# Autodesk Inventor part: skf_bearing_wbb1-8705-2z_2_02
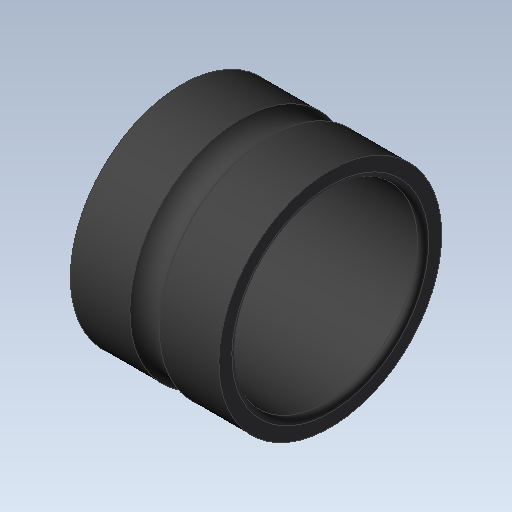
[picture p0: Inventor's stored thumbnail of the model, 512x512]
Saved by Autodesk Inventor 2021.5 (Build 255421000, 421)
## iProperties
Created: 2023-11
Part Number: skf_bearing_wbb1-8705-2z_2_02
Checked By: TraceParts S.A.
Material: Generic
Catalog Web Link: www.traceparts.com
Document SubType Name: Modeling
Designer: TraceParts
Density: 1 g/cm^3
Appearance: Default
Company: TraceParts S.A.
Author: TraceParts
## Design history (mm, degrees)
feature "skf_bearing_wbb1-8705-2z_2_02.ipt"
body "Solid1"
